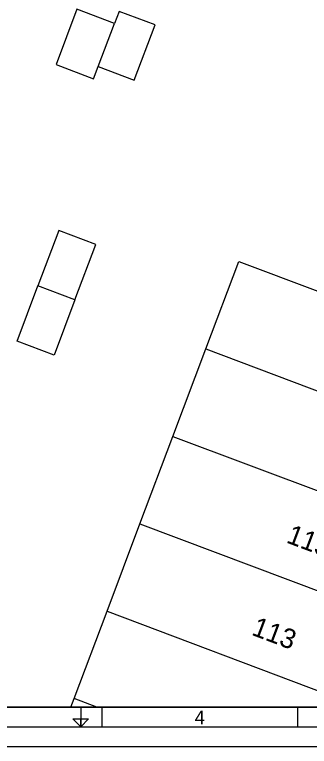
# Model space of a CAD drawing. Extents: x 192672 to 192910, y 446344 to 446512.
# Drawn here: x 192696.17 to 192711.22, y 446343.56 to 446380.91 of the extents above; entities that cross this region are included whole.
import ezdxf

# ---------------------------------------------------------------- set-up
doc = ezdxf.new("R2010")
doc.units = 0
for name, color, linetype in [('1010 viewport', 7, 'Continuous'), ('huisnummerreeks BGT', 7, 'Continuous'), ('pand op maaiveld vlak', 7, 'Continuous'), ('X-XX-AL-TEKENBLAD-S', 7, 'Continuous')]:
    doc.layers.add(name, color=color, linetype=linetype)

msp = doc.modelspace()

# ---------------------------------------------------------------- linework, layer by layer
at = {"layer": '1010 viewport'}
msp.add_lwpolyline([(192675.743, 446509.756), (192860.643, 446509.756), (192860.643, 446345.556), (192675.743, 446345.556)], close=True, dxfattribs=at)
at = {"layer": 'pand op maaiveld vlak'}
for p, q in [((192700.434, 446378.254), (192701.268, 446380.461)), ((192699.252, 446366.354), (192697.362, 446367.067)), ((192704.254, 446359.382), (192705.936, 446363.845)), ((192705.936, 446363.845), (192717.127, 446359.628)), ((192702.572, 446354.92), (192704.254, 446359.382)), ((192704.254, 446359.382), (192715.445, 446355.165)), ((192700.89, 446350.458), (192702.572, 446354.92)), ((192702.572, 446354.92), (192713.764, 446350.703)), ((192699.208, 446345.995), (192700.89, 446350.458)), ((192700.89, 446350.458), (192712.083, 446346.24)), ((192699.042, 446345.556), (192699.208, 446345.995)), ((192700.374, 446345.556), (192699.208, 446345.995))]:
    msp.add_line(p, q, dxfattribs=at)
for points in [[(192701.268, 446380.461), (192699.351, 446381.186), (192698.283, 446378.361), (192700.201, 446377.636), (192700.434, 446378.254)], [(192700.434, 446378.254), (192702.277, 446377.557), (192703.344, 446380.382), (192701.502, 446381.078), (192701.268, 446380.461)], [(192699.252, 446366.354), (192700.317, 446369.18), (192698.427, 446369.892), (192697.362, 446367.067)], [(192705.936, 446363.845), (192707.619, 446368.308), (192711.656, 446366.786), (192718.809, 446364.09), (192717.127, 446359.628)], [(192699.252, 446366.354), (192698.186, 446363.528), (192696.296, 446364.241), (192697.362, 446367.067)]]:
    msp.add_lwpolyline(points, dxfattribs=at)
at = {"layer": 'X-XX-AL-TEKENBLAD-S'}
for p, q in [((192699.543, 446345.556), (192699.543, 446344.556)), ((192700.643, 446344.556), (192700.643, 446345.556)), ((192710.643, 446344.556), (192710.643, 446345.556)), ((192699.543, 446344.956), (192699.543, 446344.556)), ((192699.543, 446344.556), (192699.543, 446344.956)), ((192674.743, 446344.556), (192908.543, 446344.556)), ((192671.743, 446343.556), (192909.543, 446343.556))]:
    msp.add_line(p, q, dxfattribs=at)
msp.add_lwpolyline([(192675.743, 446345.556), (192907.543, 446345.556), (192907.543, 446509.756), (192675.743, 446509.756)], close=True, dxfattribs=at)
for points in [[(192699.543, 446344.556), (192699.143, 446344.956), (192699.543, 446344.956)], [(192699.543, 446344.956), (192699.943, 446344.956), (192699.543, 446344.556)]]:
    msp.add_lwpolyline(points, dxfattribs=at)

# ---------------------------------------------------------------- texts
at = {"layer": 'huisnummerreeks BGT'}
for s, p in [('115', (192709.999, 446353.974)), ('113', (192708.224, 446349.261))]:
    msp.add_text(s, height=1, rotation=339.4, dxfattribs=at).set_placement(p)
at = {"layer": 'X-XX-AL-TEKENBLAD-S'}
msp.add_text('4', height=0.7, dxfattribs=at).set_placement((192705.364, 446344.685))

doc.saveas('drawing.dxf')
